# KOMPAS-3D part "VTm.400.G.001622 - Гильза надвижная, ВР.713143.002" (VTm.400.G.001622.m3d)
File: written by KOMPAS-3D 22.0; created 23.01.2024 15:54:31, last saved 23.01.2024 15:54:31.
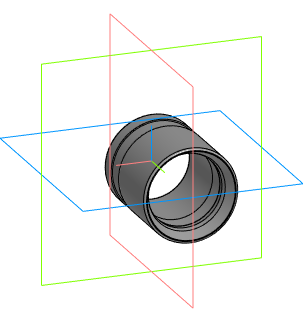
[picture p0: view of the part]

Document properties: Автор: Boss; Полное имя файла: H:\ТО\Чертежи\Для проектировщиков\VTm.400.G\stp\VTm.400.G.001622.m3d

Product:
- Part/product: VTm.400.G.001622 - Гильза надвижная  | designation ВР.713143.002

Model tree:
1. Операция без истории:1

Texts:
  ВР.713143.002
